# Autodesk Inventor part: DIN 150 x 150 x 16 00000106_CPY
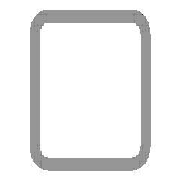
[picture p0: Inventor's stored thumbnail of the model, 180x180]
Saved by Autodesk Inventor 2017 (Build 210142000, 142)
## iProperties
Created: 2017-11
Part Number: DIN 150 x 150 x 16 00000106_CPY
Material: Steel, Mild
Description: Cold formed welded structural hollow sections of non-alloy and fine grain structural steel
Document SubType Name: Modeling
Standard: DIN
Designer: iusti
Standard Revision: 2006-07
Standards Organization: DIN
Language: en-US
Size Designation: 150 x 150 x 16
Categories: <MemberInstance><Categories><Category DisplayName="Structural Shapes" InternalName="089c4875-fa83-4c05-b084-43b9cc11f5ed" Mnemonic="GRDR"><CategoryParameter Dis
Stock Number: 150 x 150 x 16
Mass: 88044.5 g
Surface Area: 14205.2 cm^2
Volume: 11215.9 cm^3
Density: 7.85 g/cm^3
Appearance: Semi-Polished
IsCustomPart: 1
G_W: 150.000 mm
G_H: 150.000 mm
G_L: 1602.478 mm
+346FD258-9F9C-4BDE-884E-4FE9BE76FCEA+CUTDETAIL2: Miter 69.88 deg
+B95BDB02-C4C2-4ECB-9363-19BA39C44CCB+CUTDETAIL3: Miter 45.00 deg
_CCFamilyMember: 76
_CCFamilyDisplayName: DIN EN 10219-2 (Square Hollow Section - Cold Formed) - Cold formed welded structural hollow sections of non-alloy and fine grain structural steel
_FrameMemberDoc: Frame Member File
_Version: 15.0.0
_GetPNFromCC: 1
Author: iusti
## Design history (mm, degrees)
node "Start plane"
node "End plane"
sketch "Sketch"
  geometry: L1 (-75, -27)-(-75, 27); L2 (-27, 75)-(27, 75); L3 (75, 27)-(75, -27); L4 (27, -75)-(-27, -75); L5 (-27, 59)-(27, 59); L6 (59, 27)-(59, -27); L7 (27, -59)-(-27, -59); L8 (-59, -27)-(-59, 27); L9 (0, 118.918)-(0, -118.918) reference; L10 (-118.918, 0)-(118.918, 0) reference; A1 r 48 centre (-27, -27) between (-75, -27) and (-27, -75); A2 r 48 centre (-27, 27) between (-27, 75) and (-75, 27); A3 r 48 centre (27, 27) between (75, 27) and (27, 75); A4 r 48 centre (27, -27) between (27, -75) and (75, -27); A5 r 32 centre (-27, 27) between (-27, 59) and (-59, 27); A6 r 32 centre (27, 27) between (59, 27) and (27, 59); A7 r 32 centre (27, -27) between (27, -59) and (59, -27); A8 r 32 centre (-27, -27) between (-59, -27) and (-27, -59)
  constraints: 16 end point, 16 point on circle, 8 centre point, 8 tangent, 4 parallel, 3 equal radius, 2 perpendicular, 7 other
  dimensions: "d7" = 48 radius of A1 (= G_IR); "d10" = 150 distance between parallel lines of L2 L4 (= G_H); "d11" = 150 distance between parallel lines of L1 L3 (= G_W); "d12" = 16 distance between parallel lines of L3 L6 (= G_T); "d15" = 75 distance between parallel lines of L2 L10 (= 0.5 x d10); "d16" = 75 distance between parallel lines of L9 L3 (= 0.5 x d11)
extrude "Body" new body sketch "Sketch" stored distance "d3" = 1602.4779 (= G_L); taper "d4" = 0 deg
node "Driven Length"
  sketch "Sketch3"
    geometry: L1 (0, 0)-(10, 0) reference
    constraints: 2 end point, 1 horizontal
  workplane "Work Plane3"
  sketch "Sketch4"
    geometry: L1 (-2, -75)-(12, -75) reference; L2 (-2, 1527.478)-(12, 1527.478) reference
    dimensions: "d18" = 1602.4779 distance between parallel lines of L1 L2 (derived)
workplane "Work Plane5"
split "Split2"
workplane "Work Plane6"
split "Split3"
body "Solid1"
other parameters: "G_W" = 150 [user parameter; used in 1 equation term], "G_H" = 150 [user parameter; used in 1 equation term], "G_T" = 16 [user parameter; used in 1 equation term], "G_IR" = 48 [user parameter; used in 1 equation term], "G_L" = 1602.4779 (= d18) [user parameter; used in 1 equation term], "G_OFFSET_START" = 75 [user parameter; used in 1 equation term], "G_OFFSET_END" = 27.4779 [user parameter; used in 1 equation term], "d13" = -75 (= -G_OFFSET_START), "d14" = 1527.4779 (= G_OFFSET_END + B_L), "d17" = 90 deg
